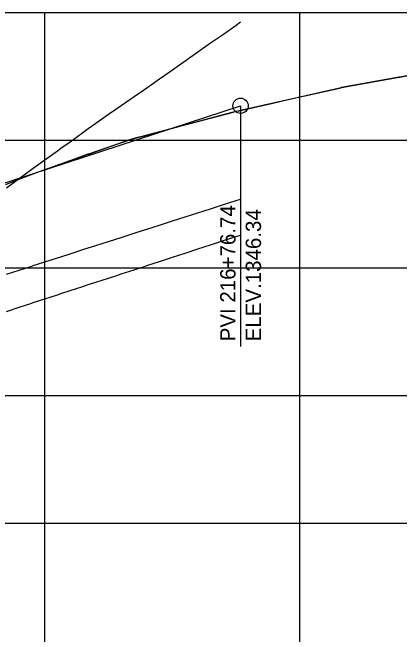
# Model space of a CAD drawing. Extents: x 1371206 to 1374178, y 379328 to 381511.
# Drawn here: x 1372832 to 1372983.6, y 379554.7 to 379798.4 of the extents above; entities that cross this region are included whole.
import ezdxf

# ---------------------------------------------------------------- set-up
doc = ezdxf.new("R2010")
doc.units = 0
for name, color, linetype in [('37', 7, 'Continuous'), ('R_Exist Surface', 7, 'Continuous'), ('R_Profile Work Left', 7, 'Continuous'), ('R_Profile Work Right', 7, 'Continuous'), ('R_Vert Alg', 7, 'Continuous'), ('R_Vert Alg Annot', 7, 'Continuous')]:
    doc.layers.add(name, color=color, linetype=linetype)

msp = doc.modelspace()

# ---------------------------------------------------------------- linework, layer by layer
at = {"layer": '37'}
for p, q in [((1371244.63, 379798.35), (1374144.63, 379798.35)), ((1371244.63, 379798.35), (1374144.63, 379798.35)), ((1372844.63, 379348.35), (1372844.63, 379798.35)), ((1372944.63, 379348.35), (1372944.63, 379798.35)), ((1371244.63, 379748.35), (1374144.63, 379748.35)), ((1371244.63, 379698.35), (1374144.63, 379698.35)), ((1371244.63, 379648.35), (1374144.63, 379648.35)), ((1371244.63, 379598.35), (1372944.63, 379598.35)), ((1371244.63, 379598.35), (1374144.63, 379598.35))]:
    msp.add_line(p, q, dxfattribs=at)
at = {"layer": 'R_Exist Surface'}
for points in [[(1372829.39, 379730.98), (1372834.87, 379733.17), (1372840.17, 379735.16), (1372842.57, 379736.05), (1372850.94, 379739.02), (1372856.44, 379740.96), (1372861.72, 379742.92), (1372861.93, 379742.99), (1372872.49, 379746.69), (1372877.98, 379748.6), (1372881.11, 379749.46), (1372883.27, 379750.03), (1372898.6, 379754.13), (1372918.07, 379759.32), (1372919.15, 379759.61), (1372920.79, 379759.98), (1372933.54, 379762.86), (1372939.96, 379764.31), (1372940, 379764.31), (1372960.76, 379769), (1372960.95, 379769.03), (1372983.44, 379773.09), (1372983.58, 379773.11), (1373006.13, 379777.18)], [(1372844.63, 379736.67), (1372850.94, 379738.9), (1372856.44, 379740.84), (1372861.72, 379742.8), (1372861.93, 379742.88), (1372872.49, 379746.57), (1372877.98, 379748.48), (1372881.11, 379749.34), (1372883.27, 379749.92), (1372898.6, 379754.01), (1372918.07, 379759.21), (1372919.15, 379759.49), (1372920.79, 379759.86), (1372933.54, 379762.74), (1372939.96, 379764.19), (1372940, 379764.2), (1372960.76, 379768.88), (1372960.95, 379768.91), (1372983.44, 379772.97), (1372983.58, 379772.99), (1373006.13, 379777.06)]]:
    msp.add_lwpolyline(points, dxfattribs=at)
at = {"layer": 'R_Profile Work Left'}
for points in [[(1372829.63, 379729.61), (1372834.63, 379733.26), (1372839.63, 379736.91), (1372840.17, 379737.3), (1372844.63, 379740.56), (1372849.63, 379744.21), (1372850.94, 379745.19), (1372854.63, 379747.69), (1372859.63, 379751.32), (1372861.72, 379752.84), (1372864.63, 379754.95), (1372869.63, 379758.51), (1372872.49, 379760.48), (1372874.63, 379761.95), (1372879.63, 379765.39), (1372883.27, 379767.89), (1372884.63, 379768.85), (1372889.63, 379772.36), (1372894.63, 379775.86), (1372899.63, 379779.37), (1372904.63, 379782.88), (1372909.63, 379786.39), (1372914.63, 379789.89), (1372919.63, 379793.4), (1372921.37, 379794.62)], [(1372829.63, 379681.27), (1372834.63, 379682.9), (1372839.63, 379684.53), (1372840.17, 379684.71), (1372844.63, 379686.16), (1372849.63, 379687.79), (1372850.94, 379688.22), (1372854.63, 379689.42), (1372859.63, 379691.05), (1372861.72, 379691.73), (1372864.63, 379692.68), (1372869.63, 379694.31), (1372872.49, 379695.25), (1372874.63, 379695.94), (1372879.63, 379697.57), (1372883.27, 379698.76), (1372884.63, 379699.2), (1372889.63, 379700.83), (1372894.63, 379702.46), (1372899.63, 379704.09), (1372904.63, 379705.72), (1372909.63, 379707.35), (1372914.63, 379708.98), (1372919.63, 379710.61), (1372921.37, 379711.18)]]:
    msp.add_lwpolyline(points, dxfattribs=at)
at = {"layer": 'R_Profile Work Right'}
msp.add_lwpolyline([(1372829.63, 379695.81), (1372834.63, 379697.42), (1372839.63, 379699.02), (1372840.17, 379699.19), (1372844.63, 379700.62), (1372849.63, 379702.23), (1372850.94, 379702.65), (1372854.63, 379703.83), (1372859.63, 379705.44), (1372861.72, 379706.11), (1372864.63, 379707.04), (1372869.63, 379708.65), (1372872.49, 379709.57), (1372874.63, 379710.25), (1372879.63, 379711.86), (1372883.27, 379713.02), (1372884.63, 379713.46), (1372889.63, 379715.07), (1372894.63, 379716.67), (1372899.63, 379718.27), (1372904.63, 379719.88), (1372909.63, 379721.48), (1372914.63, 379723.09), (1372919.63, 379724.69), (1372921.37, 379725.25)], dxfattribs=at)
at = {"layer": 'R_Vert Alg'}
msp.add_line((1372719.63, 379696.01), (1372921.37, 379761.78), dxfattribs=at)
msp.add_circle((1372921.37, 379761.78), 3, dxfattribs=at)
at = {"layer": 'R_Vert Alg Annot'}
msp.add_line((1372921.37, 379761.78), (1372921.37, 379667.46), dxfattribs=at)

# ---------------------------------------------------------------- texts
for s, p in [('PVI 216+76.74', (1372919.37, 379669.53)), ('ELEV.1346.34', (1372929.37, 379669.53))]:
    msp.add_text(s, height=6, rotation=90, dxfattribs=at).set_placement(p)

doc.saveas('drawing.dxf')
